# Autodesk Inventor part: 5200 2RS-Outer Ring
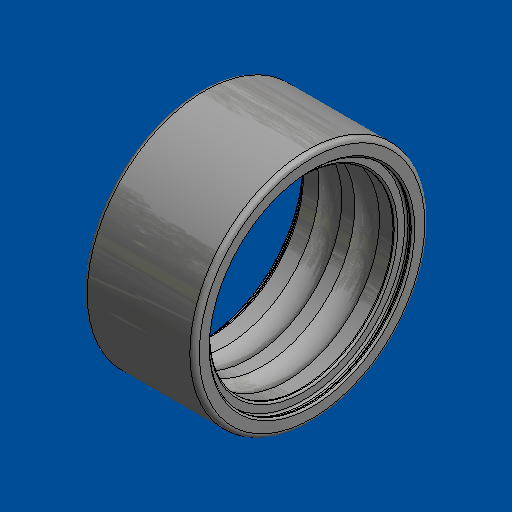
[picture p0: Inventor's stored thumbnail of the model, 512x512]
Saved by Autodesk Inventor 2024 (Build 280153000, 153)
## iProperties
Part Number: 5200 2RS-Outer Ring
Material: Generic
Document SubType Name: Modeling
Designer: amoles
Appearance: Default
Author: amoles
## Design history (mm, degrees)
feature "5200 2RS-Outer Ring"
body "Solid1"
